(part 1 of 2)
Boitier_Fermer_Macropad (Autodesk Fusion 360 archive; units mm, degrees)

design "Coque/BoitierFermer v2" references "PCB5_Complex_Finale_Design"
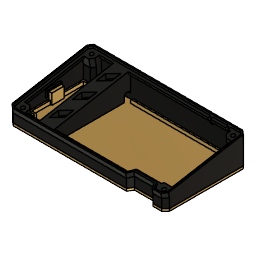
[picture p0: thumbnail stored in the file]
component_insert "Insertion d'un composant"
position "Position1"
sketch "Esquisse1" plane through (0, -7.3332, 41.5887) normal (0, 0.1736, -0.9848) x axis (-1, 0, 0)
  line L1 (-116.0418, -59.8204) -> (2.9981, -59.8204)
  line L2 (-118.0975, -61.9871) -> (-116.0418, -59.8204)
  line L3 (-118.0975, -121.6516) -> (-118.0975, -61.9871)
  line L4 (-115.692, -124.0571) -> (-118.0975, -121.6516)
  line L5 (-109.9203, -124.0571) -> (-115.692, -124.0571)
  line L6 (-107.7697, -120.1267) -> (-109.9203, -124.0571)
  line L7 (-89.721, -120.1201) -> (-107.7585, -120.1201)
  line L8 (-87.2075, -124.1841) -> (-89.7102, -120.1262)
  line L9 (3.0963, -124.1841) -> (-87.2075, -124.1841)
  line L10 (5.0673, -122.5451) -> (3.0963, -124.1841)
  line L11 (5.0673, -61.9929) -> (5.0673, -122.5451)
  line L12 (2.9981, -59.8204) -> (5.0673, -61.9929)
  line L13 (-2.3851, -76.6358) -> (-2.3851, -77.8358)
  line L14 (-0.3851, -77.8358) -> (-0.3851, -76.6358)
  line L15 (-13.585, -76.6358) -> (-13.585, -77.8358)
  line L16 (-11.585, -77.8358) -> (-11.585, -76.6358)
  line L17 (-109.1497, -125.3571) -> (-116.2304, -125.3571)
  line L18 (-106.9955, -121.4201) -> (-109.1497, -125.3571)
  line L19 (-90.4395, -121.4201) -> (-106.9955, -121.4201)
  line L20 (-87.9332, -125.4841) -> (-90.4395, -121.4201)
  line L21 (3.5662, -125.4841) -> (-87.9332, -125.4841)
  line L22 (6.3673, -123.1548) -> (3.5662, -125.4841)
  line L23 (6.3673, -61.4728) -> (6.3673, -123.1548)
  line L24 (3.5552, -58.5204) -> (6.3673, -61.4728)
  line L25 (-116.6004, -58.5204) -> (3.5552, -58.5204)
  line L26 (-119.3975, -61.4686) -> (-116.6004, -58.5204)
  line L27 (-119.3975, -122.1901) -> (-119.3975, -61.4686)
  line L28 (-116.2304, -125.3571) -> (-119.3975, -122.1901)
  line L29 (-107.4241, -120.1201) -> (-109.7424, -124.3571)
  line L30 (-107.5882, -120.4201) -> (-109.7424, -124.3571)
  line L31 (-109.7424, -124.3571) -> (-115.8162, -124.3571)
  line L32 (-115.8162, -124.3571) -> (-118.3975, -121.7758)
  line L33 (-118.3975, -121.7758) -> (-118.3975, -61.8675)
  line L34 (-118.3975, -61.8675) -> (-116.1707, -59.5204)
  line L35 (-116.1707, -59.5204) -> (3.1266, -59.5204)
  line L36 (3.1266, -59.5204) -> (5.3673, -61.8729)
  line L37 (5.3673, -61.8729) -> (5.3673, -122.6858)
  line L38 (5.3673, -122.6858) -> (3.2047, -124.4841)
  line L39 (3.2047, -124.4841) -> (-87.375, -124.4841)
  line L40 (-87.375, -124.4841) -> (-89.8813, -120.4201)
  line L41 (-90.0663, -120.1201) -> (-87.375, -124.4841)
  line L42 (-107.4241, -120.1201) -> (-90.0663, -120.1201)
  arc A1 centre (-107.7585, -120.1328) radius 0.0127 clockwise from (-107.7697, -120.1267) to (-107.7585, -120.1201)
  arc A2 centre (-89.721, -120.1328) radius 0.0127 clockwise from (-89.721, -120.1201) to (-89.7102, -120.1262)
  circle C1 centre (0.5, -63.7757) radius 1
  circle C2 centre (0.5, -120.2758) radius 1
  circle C3 centre (-6.985, -107.3058) radius 8.05
  arc A3 centre (-1.3851, -76.6358) radius 1 clockwise from (-2.3851, -76.6358) to (-0.3851, -76.6358)
  arc A4 centre (-1.3851, -77.8358) radius 1 clockwise from (-0.3851, -77.8358) to (-2.3851, -77.8358)
  circle C4 centre (-4.4849, -70.2356) radius 0.5
  circle C5 centre (-4.485, -84.7356) radius 0.5
  circle C6 centre (-6.985, -84.7356) radius 0.5
  circle C7 centre (-9.4849, -70.2356) radius 0.5
  circle C8 centre (-9.485, -84.7356) radius 0.5
  arc A5 centre (-12.585, -76.6358) radius 1 clockwise from (-13.585, -76.6358) to (-11.585, -76.6358)
  arc A6 centre (-12.585, -77.8358) radius 1 clockwise from (-11.585, -77.8358) to (-13.585, -77.8358)
  circle C9 centre (-31.0949, -91.1329) radius 1
  circle C10 centre (-31.0949, -72.0827) radius 1
  circle C11 centre (-31.0949, -110.1829) radius 1
  circle C12 centre (-36.5947, -91.1329) radius 1.75
  circle C13 centre (-36.5947, -72.0827) radius 1.75
  circle C14 centre (-36.5947, -110.1829) radius 1.75
  circle C15 centre (-36.5947, -85.233) radius 0.65
  circle C16 centre (-36.5947, -66.1828) radius 0.65
  circle C17 centre (-36.5947, -104.283) radius 0.65
  circle C18 centre (-37.3381, -93.8438) radius 0.1525
  circle C19 centre (-38.1001, -94.6058) radius 0.1525
  circle C20 centre (-38.7351, -95.3678) radius 0.1525
  circle C21 centre (-41.0211, -82.2868) radius 0.1525
  circle C22 centre (-41.0211, -84.3188) radius 0.1525
  circle C23 centre (-41.5948, -87.3328) radius 0.65
  circle C24 centre (-41.5948, -68.2826) radius 0.65
  circle C25 centre (-41.5948, -106.3828) radius 0.65
  circle C26 centre (-42.0949, -91.1329) radius 1
  circle C27 centre (-42.0949, -72.0827) radius 1
  circle C28 centre (-42.0949, -110.1829) radius 1
  circle C29 centre (-41.5291, -103.3688) radius 0.1525
  circle C30 centre (-41.5291, -101.2816) radius 0.1525
  circle C31 centre (-50.1452, -91.1329) radius 1
  circle C32 centre (-50.1452, -72.0827) radius 1
  circle C33 centre (-50.1452, -110.1829) radius 1
  circle C34 centre (-55.6451, -91.1329) radius 1.75
  circle C35 centre (-55.6451, -72.0827) radius 1.75
  circle C36 centre (-55.6451, -110.1829) radius 1.75
  circle C37 centre (-55.645, -85.233) radius 0.65
  circle C38 centre (-55.645, -66.1828) radius 0.65
  circle C39 centre (-55.645, -104.283) radius 0.65
  circle C40 centre (-60.1023, -84.2876) radius 0.1525
  circle C41 centre (-60.1023, -82.2556) radius 0.1525
  circle C42 centre (-60.6452, -87.3328) radius 0.65
  circle C43 centre (-60.6452, -68.2826) radius 0.65
  circle C44 centre (-60.6452, -106.3828) radius 0.65
  circle C45 centre (-61.1452, -91.1329) radius 1
  circle C46 centre (-61.1452, -72.0827) radius 1
  circle C47 centre (-61.1452, -110.1829) radius 1
  circle C48 centre (-60.5791, -101.3092) radius 0.1525
  circle C49 centre (-60.5791, -103.3964) radius 0.1525
  circle C50 centre (-69.1953, -91.1329) radius 1
  circle C51 centre (-69.1953, -72.0827) radius 1
  circle C52 centre (-69.1953, -110.1829) radius 1
  circle C53 centre (-74.6952, -91.1329) radius 1.75
  circle C54 centre (-74.6952, -72.0827) radius 1.75
  circle C55 centre (-74.6952, -110.1829) radius 1.75
  circle C56 centre (-74.6951, -85.233) radius 0.65
  circle C57 centre (-74.6951, -66.1828) radius 0.65
  circle C58 centre (-74.6951, -104.283) radius 0.65
  circle C59 centre (-78.7402, -95.3678) radius 0.1525
  circle C60 centre (-79.0883, -84.3357) radius 0.1525
  circle C61 centre (-79.1049, -82.2399) radius 0.1525
  circle C62 centre (-79.6953, -87.3328) radius 0.65
  circle C63 centre (-79.6953, -68.2826) radius 0.65
  circle C64 centre (-79.6953, -106.3828) radius 0.65
  circle C65 centre (-80.1953, -91.1329) radius 1
  circle C66 centre (-80.1953, -72.0827) radius 1
  circle C67 centre (-80.1953, -110.1829) radius 1
  circle C68 centre (-79.5022, -94.6058) radius 0.1525
  circle C69 centre (-79.6292, -101.1822) radius 0.1525
  circle C70 centre (-79.6292, -103.2694) radius 0.1525
  circle C71 centre (-80.2642, -93.8438) radius 0.1525
  circle C72 centre (-86.1062, -92.9548) radius 0.1525
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  point P156 (-107.4241, -120.1201)
  point P169 (-90.0663, -120.1201)
  coincident L7 P156
  coincident L7 P169
  parallel L40 L41
  dimension "d1" = 0.3
  dimension "d2" = 1.3 (= "1.00 mm + 0.3 mm")
  dimension "d3" = 0.3
extrude "Extrusion1" new body sketch "Esquisse1" profile of L7 L28 L25 L18 L23 L20 L22 L26 L21 L19 L27 L24 L17 L29 L32 L30 L33 L31 L34 L37 L40 L39 L38 L36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 against normal blind 1.7
sketch "Esquisse2" plane through (0, -7.3332, 41.5887) normal (0, 0.1736, -0.9848) x axis (-1, 0, 0)
  line L1 (-87.375, -124.4841) -> (3.2047, -124.4841)
  line L2 (-90.0663, -120.1201) -> (-87.375, -124.4841)
  line L3 (-107.4241, -120.1201) -> (-90.0663, -120.1201)
  line L4 (-109.7424, -124.3571) -> (-107.4241, -120.1201)
  line L5 (-115.8162, -124.3571) -> (-109.7424, -124.3571)
  line L6 (-118.3975, -121.7758) -> (-115.8162, -124.3571)
  line L7 (-118.3975, -61.8675) -> (-118.3975, -121.7758)
  line L8 (-116.1707, -59.5204) -> (-118.3975, -61.8675)
  line L9 (3.1266, -59.5204) -> (-116.1707, -59.5204)
  line L10 (5.3673, -61.8729) -> (3.1266, -59.5204)
  line L11 (5.3673, -122.6858) -> (5.3673, -61.8729)
  line L12 (3.2047, -124.4841) -> (5.3673, -122.6858)
  line L13 (-116.2304, -125.3571) -> (-119.3975, -122.1901)
  line L14 (-109.1497, -125.3571) -> (-116.2304, -125.3571)
  line L15 (-106.9955, -121.4201) -> (-109.1497, -125.3571)
  line L16 (-90.4395, -121.4201) -> (-106.9955, -121.4201)
  line L17 (-87.9332, -125.4841) -> (-90.4395, -121.4201)
  line L18 (3.5662, -125.4841) -> (-87.9332, -125.4841)
  line L19 (6.3673, -123.1548) -> (3.5662, -125.4841)
  line L20 (6.3673, -61.4728) -> (6.3673, -123.1548)
  line L21 (3.5552, -58.5204) -> (6.3673, -61.4728)
  line L22 (-116.6004, -58.5204) -> (3.5552, -58.5204)
  line L23 (-119.3975, -61.4686) -> (-116.6004, -58.5204)
  line L24 (-119.3975, -122.1901) -> (-119.3975, -61.4686)
  line L25 (-86.0912, -122.1841) -> (2.3734, -122.1841)
  line L26 (-88.7826, -117.8201) -> (-86.0912, -122.1841)
  line L27 (-108.7874, -117.8201) -> (-88.7826, -117.8201)
  line L28 (-111.1057, -122.0571) -> (-108.7874, -117.8201)
  line L29 (-114.8635, -122.0571) -> (-111.1057, -122.0571)
  line L30 (-116.0975, -120.8232) -> (-114.8635, -122.0571)
  line L31 (-116.0975, -62.7849) -> (-116.0975, -120.8232)
  line L32 (-115.1824, -61.8204) -> (-116.0975, -62.7849)
  line L33 (2.141, -61.8204) -> (-115.1824, -61.8204)
  line L34 (3.0673, -62.7929) -> (2.141, -61.8204)
  line L35 (3.0673, -121.6071) -> (3.0673, -62.7929)
  line L36 (2.3734, -122.1841) -> (3.0673, -121.6071)
  dimension "d6" = 2.3 (= "2.00 mm + 0.3 mm")
extrude "Extrusion2" add sketch "Esquisse2" along normal blind 2
position "Position2"
work_plane "Plan de construction1" RotateAngle 0
sketch "Esquisse3" plane through (0, 0, 17.829) normal (0, 0, 1) x axis (1, 0, 0)
  line L1 (-3.0673, -126.7455) -> (-3.0673, -68.8249)
  line L2 (-2.3734, -127.3138) -> (-3.0673, -126.7455)
  line L3 (86.0912, -127.3138) -> (-2.3734, -127.3138)
  line L4 (88.7826, -123.0161) -> (86.0912, -127.3138)
  line L5 (108.7874, -123.0161) -> (88.7826, -123.0161)
  line L6 (111.1057, -127.1887) -> (108.7874, -123.0161)
  line L7 (114.8635, -127.1887) -> (111.1057, -127.1887)
  line L8 (116.0975, -125.9735) -> (114.8635, -127.1887)
  line L9 (116.0975, -68.817) -> (116.0975, -125.9735)
  line L10 (115.1824, -67.8671) -> (116.0975, -68.817)
  line L11 (-2.141, -67.8671) -> (115.1824, -67.8671)
  line L12 (-3.0673, -68.8249) -> (-2.141, -67.8671)
  line L13 (119.3975, -127.3196) -> (119.3975, -67.5206)
  line L14 (116.2304, -130.4386) -> (119.3975, -127.3196)
  line L15 (109.1497, -130.4386) -> (116.2304, -130.4386)
  line L16 (106.9955, -126.5614) -> (109.1497, -130.4386)
  line L17 (90.4395, -126.5614) -> (106.9955, -126.5614)
  line L18 (87.9332, -130.5637) -> (90.4395, -126.5614)
  line L19 (-3.5662, -130.5637) -> (87.9332, -130.5637)
  line L20 (-6.3673, -128.2697) -> (-3.5662, -130.5637)
  line L21 (-6.3673, -67.5248) -> (-6.3673, -128.2697)
  line L22 (-3.5552, -64.6173) -> (-6.3673, -67.5248)
  line L23 (116.6004, -64.6173) -> (-3.5552, -64.6173)
  line L24 (119.3975, -67.5206) -> (116.6004, -64.6173)
extrude "Extrusion3" new body sketch "Esquisse3" against normal blind 1
sketch "Esquisse4" plane through (0, 0, 17.829) normal (0, 0, 1) x axis (-1, 0, 0)
  line L1 (2.141, 67.8671) -> (3.0673, 68.8249)
  line L2 (-115.1824, 67.8671) -> (2.141, 67.8671)
  line L3 (-116.0975, 68.817) -> (-115.1824, 67.8671)
  line L4 (-116.0975, 125.9735) -> (-116.0975, 68.817)
  line L5 (-114.8635, 127.1887) -> (-116.0975, 125.9735)
  line L6 (-111.1057, 127.1887) -> (-114.8635, 127.1887)
  line L7 (-108.7874, 123.0161) -> (-111.1057, 127.1887)
  line L8 (-88.7826, 123.0161) -> (-108.7874, 123.0161)
  line L9 (-86.0912, 127.3138) -> (-88.7826, 123.0161)
  line L10 (2.3734, 127.3138) -> (-86.0912, 127.3138)
  line L11 (3.0673, 126.7455) -> (2.3734, 127.3138)
  line L12 (3.0673, 68.8249) -> (3.0673, 126.7455)
  line L13 (3.5552, 64.6173) -> (-116.6004, 64.6173)
  line L14 (6.3673, 67.5248) -> (3.5552, 64.6173)
  line L15 (6.3673, 128.2697) -> (6.3673, 67.5248)
  line L16 (3.5662, 130.5637) -> (6.3673, 128.2697)
  line L17 (-87.9332, 130.5637) -> (3.5662, 130.5637)
  line L18 (-90.4395, 126.5614) -> (-87.9332, 130.5637)
  line L19 (-106.9955, 126.5614) -> (-90.4395, 126.5614)
  line L20 (-109.1497, 130.4386) -> (-106.9955, 126.5614)
  line L21 (-116.2304, 130.4386) -> (-109.1497, 130.4386)
  line L22 (-119.3975, 127.3196) -> (-116.2304, 130.4386)
  line L23 (-119.3975, 67.5206) -> (-119.3975, 127.3196)
  line L24 (-116.6004, 64.6173) -> (-119.3975, 67.5206)
  line L25 (2.141, 67.8671) -> (3.5552, 64.6173)
  line L26 (6.3673, 67.5248) -> (3.0673, 68.8249)
  line L27 (-115.1824, 67.8671) -> (-116.6004, 64.6173)
  line L28 (-119.3975, 67.5206) -> (-116.0975, 68.817)
  line L29 (-116.0975, 125.9735) -> (-119.3975, 127.3196)
  line L30 (-114.8635, 127.1887) -> (-116.2304, 130.4386)
  line L31 (-111.1057, 127.1887) -> (-109.1497, 130.4386)
  line L32 (-108.7874, 123.0161) -> (-106.9955, 126.5614)
  line L33 (-88.7826, 123.0161) -> (-90.4395, 126.5614)
  line L34 (-86.0912, 127.3138) -> (-87.9332, 130.5637)
  line L35 (2.3734, 127.3138) -> (3.5662, 130.5637)
  line L36 (6.3673, 128.2697) -> (3.0673, 126.7455)
  point P15 (3.5552, 64.6173)
  point P26 (3.5552, 64.6173)
  point P3 (2.141, 67.8671)
  point P27 (2.141, 67.8671)
  point P2 (3.0673, 68.8249)
  point P28 (3.0673, 68.8249)
  point P16 (6.3673, 67.5248)
  point P29 (6.3673, 67.5248)
  point P14 (-116.6004, 64.6173)
  point P30 (-116.6004, 64.6173)
  point P4 (-115.1824, 67.8671)
  point P31 (-115.1824, 67.8671)
  point P5 (-116.0975, 68.817)
  point P32 (-116.0975, 68.817)
  point P25 (-119.3975, 67.5206)
  point P33 (-119.3975, 67.5206)
  point P24 (-119.3975, 127.3196)
  point P34 (-119.3975, 127.3196)
  point P6 (-116.0975, 125.9735)
  point P35 (-116.0975, 125.9735)
  point P23 (-116.2304, 130.4386)
  point P36 (-116.2304, 130.4386)
  point P7 (-114.8635, 127.1887)
  point P37 (-114.8635, 127.1887)
  point P22 (-109.1497, 130.4386)
  point P38 (-109.1497, 130.4386)
  point P8 (-111.1057, 127.1887)
  point P39 (-111.1057, 127.1887)
  point P21 (-106.9955, 126.5614)
  point P40 (-106.9955, 126.5614)
  point P9 (-108.7874, 123.0161)
  point P41 (-108.7874, 123.0161)
  point P20 (-90.4395, 126.5614)
  point P42 (-90.4395, 126.5614)
  point P10 (-88.7826, 123.0161)
  point P43 (-88.7826, 123.0161)
  point P19 (-87.9332, 130.5637)
  point P44 (-87.9332, 130.5637)
  point P11 (-86.0912, 127.3138)
  point P45 (-86.0912, 127.3138)
  point P18 (3.5662, 130.5637)
  point P46 (3.5662, 130.5637)
  point P12 (2.3734, 127.3138)
  point P47 (2.3734, 127.3138)
  point P13 (3.0673, 126.7455)
  point P48 (3.0673, 126.7455)
  point P17 (6.3673, 128.2697)
  point P49 (6.3673, 128.2697)
  coincident P15 P26
  coincident P3 P27
  coincident P2 P28
  coincident P16 P29
  coincident P14 P30
  coincident P4 P31
  coincident P5 P32
  coincident P25 P33
  coincident P24 P34
  coincident P6 P35
  coincident P23 P36
  coincident P7 P37
  coincident P22 P38
  coincident P8 P39
  coincident P21 P40
  coincident P9 P41
  coincident P20 P42
  coincident P10 P43
  coincident P19 P44
  coincident P11 P45
  coincident P18 P46
  coincident P12 P47
  coincident P13 P48
  coincident P17 P49
sketch "Esquisse5" plane through (0, -6.9859, 39.619) normal (0, 0.1736, -0.9848) x axis (-1, 0, 0)
  line L1 (3.0673, -121.6071) -> (3.0673, -62.7929)
  line L2 (2.3734, -122.1841) -> (3.0673, -121.6071)
  line L3 (-86.0912, -122.1841) -> (2.3734, -122.1841)
  line L4 (-88.7826, -117.8201) -> (-86.0912, -122.1841)
  line L5 (-108.7874, -117.8201) -> (-88.7826, -117.8201)
  line L6 (-111.1057, -122.0571) -> (-108.7874, -117.8201)
  line L7 (-114.8635, -122.0571) -> (-111.1057, -122.0571)
  line L8 (-116.0975, -120.8232) -> (-114.8635, -122.0571)
  line L9 (-116.0975, -62.7849) -> (-116.0975, -120.8232)
  line L10 (-115.1824, -61.8204) -> (-116.0975, -62.7849)
  line L11 (2.141, -61.8204) -> (-115.1824, -61.8204)
  line L12 (3.0673, -62.7929) -> (2.141, -61.8204)
  line L13 (-119.3975, -122.1901) -> (-119.3975, -61.4686)
  line L14 (-116.2304, -125.3571) -> (-119.3975, -122.1901)
  line L15 (-109.1497, -125.3571) -> (-116.2304, -125.3571)
  line L16 (-106.9955, -121.4201) -> (-109.1497, -125.3571)
  line L17 (-90.4395, -121.4201) -> (-106.9955, -121.4201)
  line L18 (-87.9332, -125.4841) -> (-90.4395, -121.4201)
  line L19 (3.5662, -125.4841) -> (-87.9332, -125.4841)
  line L20 (6.3673, -123.1548) -> (3.5662, -125.4841)
  line L21 (6.3673, -61.4728) -> (6.3673, -123.1548)
  line L22 (3.5552, -58.5204) -> (6.3673, -61.4728)
  line L23 (-116.6004, -58.5204) -> (3.5552, -58.5204)
  line L24 (-119.3975, -61.4686) -> (-116.6004, -58.5204)
  line L25 (3.5552, -58.5204) -> (2.141, -61.8204)
  line L26 (6.3673, -61.4728) -> (3.0673, -62.7929)
  line L27 (-119.3975, -61.4686) -> (-116.0975, -62.7849)
  line L28 (-116.6004, -58.5204) -> (-115.1824, -61.8204)
  line L29 (6.3673, -123.1548) -> (3.0673, -121.6071)
  line L30 (2.3734, -122.1841) -> (3.5662, -125.4841)
  line L31 (-86.0912, -122.1841) -> (-87.9332, -125.4841)
  line L32 (-88.7826, -117.8201) -> (-90.4395, -121.4201)
  line L33 (-108.7874, -117.8201) -> (-106.9955, -121.4201)
  line L34 (-111.1057, -122.0571) -> (-109.1497, -125.3571)
  line L35 (-114.8635, -122.0571) -> (-116.2304, -125.3571)
  line L36 (-119.3975, -122.1901) -> (-116.0975, -120.8232)
  point P13 (2.141, -61.8204)
  point P26 (2.141, -61.8204)
  point P24 (3.5552, -58.5204)
  point P27 (3.5552, -58.5204)
  point P2 (3.0673, -62.7929)
  point P28 (3.0673, -62.7929)
  point P23 (6.3673, -61.4728)
  point P29 (6.3673, -61.4728)
  point P11 (-116.0975, -62.7849)
  point P30 (-116.0975, -62.7849)
  point P14 (-119.3975, -61.4686)
  point P31 (-119.3975, -61.4686)
  point P12 (-115.1824, -61.8204)
  point P32 (-115.1824, -61.8204)
  point P25 (-116.6004, -58.5204)
  point P33 (-116.6004, -58.5204)
  point P3 (3.0673, -121.6071)
  point P34 (3.0673, -121.6071)
  point P22 (6.3673, -123.1548)
  point P35 (6.3673, -123.1548)
  point P21 (3.5662, -125.4841)
  point P36 (3.5662, -125.4841)
  point P4 (2.3734, -122.1841)
  point P37 (2.3734, -122.1841)
  point P20 (-87.9332, -125.4841)
  point P38 (-87.9332, -125.4841)
  point P5 (-86.0912, -122.1841)
  point P39 (-86.0912, -122.1841)
  point P19 (-90.4395, -121.4201)
  point P40 (-90.4395, -121.4201)
  point P6 (-88.7826, -117.8201)
  point P41 (-88.7826, -117.8201)
  point P18 (-106.9955, -121.4201)
  point P42 (-106.9955, -121.4201)
  point P7 (-108.7874, -117.8201)
  point P43 (-108.7874, -117.8201)
  point P17 (-109.1497, -125.3571)
  point P44 (-109.1497, -125.3571)
  point P8 (-111.1057, -122.0571)
  point P45 (-111.1057, -122.0571)
  point P16 (-116.2304, -125.3571)
  point P46 (-116.2304, -125.3571)
  point P9 (-114.8635, -122.0571)
  point P47 (-114.8635, -122.0571)
  point P10 (-116.0975, -120.8232)
  point P48 (-116.0975, -120.8232)
  point P15 (-119.3975, -122.1901)
  point P49 (-119.3975, -122.1901)
  coincident P13 P26
  coincident P24 P27
  coincident P2 P28
  coincident P23 P29
  coincident P11 P30
  coincident P14 P31
  coincident P12 P32
  coincident P25 P33
  coincident P3 P34
  coincident P22 P35
  coincident P21 P36
  coincident P4 P37
  coincident P20 P38
  coincident P5 P39
  coincident P19 P40
  coincident P6 P41
  coincident P18 P42
  coincident P7 P43
  coincident P17 P44
  coincident P8 P45
  coincident P16 P46
  coincident P9 P47
  coincident P10 P48
  coincident P15 P49
loft "Lissage1" sketch "Esquisse4" + "Esquisse5"
loft "Lissage2" sketch "Esquisse4" + "Esquisse5"
loft "Lissage3" sketch "Esquisse5" + "Esquisse4"
loft "Lissage4" sketch "Esquisse4" + "Esquisse5"
loft "Lissage7" sketch "Esquisse4" + "Esquisse5"
loft "Lissage8" sketch "Esquisse4" + "Esquisse5"
loft "Lissage9" sketch "Esquisse4" + "Esquisse5"
loft "Lissage10" sketch "Esquisse4" + "Esquisse5"
loft "Lissage11" sketch "Esquisse4" + "Esquisse5"
loft "Lissage12" sketch "Esquisse4" + "Esquisse5"
loft "Lissage13" sketch "Esquisse5" + "Esquisse4"
loft "Lissage14" sketch "Esquisse4" + "Esquisse5"
combine "Combiner"
sketch "Esquisse6" plane through (0, -7.6284, 43.2628) normal (0, -0.1736, 0.9848) x axis (1, 0, 0)
  line L1 (-3.2047, -124.4841) -> (87.375, -124.4841)
  line L2 (-5.3673, -122.6858) -> (-3.2047, -124.4841)
  line L3 (-5.3673, -61.8729) -> (-5.3673, -122.6858)
  line L4 (-3.1266, -59.5204) -> (-5.3673, -61.8729)
  line L5 (116.1707, -59.5204) -> (-3.1266, -59.5204)
  line L6 (118.3975, -61.8675) -> (116.1707, -59.5204)
  line L7 (118.3975, -121.7758) -> (118.3975, -61.8675)
  line L8 (115.8162, -124.3571) -> (118.3975, -121.7758)
  line L9 (109.7424, -124.3571) -> (115.8162, -124.3571)
  line L10 (107.4241, -120.1201) -> (109.7424, -124.3571)
  line L11 (90.0663, -120.1201) -> (107.4241, -120.1201)
  line L12 (87.375, -124.4841) -> (90.0663, -120.1201)
  line L13 (119.3975, -122.1901) -> (116.2304, -125.3571)
  line L14 (119.3975, -61.4686) -> (119.3975, -122.1901)
  line L15 (116.6004, -58.5204) -> (119.3975, -61.4686)
  line L16 (-3.5552, -58.5204) -> (116.6004, -58.5204)
  line L17 (-6.3673, -61.4728) -> (-3.5552, -58.5204)
  line L18 (-6.3673, -123.1548) -> (-6.3673, -61.4728)
  line L19 (-3.5662, -125.4841) -> (-6.3673, -123.1548)
  line L20 (87.9332, -125.4841) -> (-3.5662, -125.4841)
  line L21 (90.4395, -121.4201) -> (87.9332, -125.4841)
  line L22 (106.9955, -121.4201) -> (90.4395, -121.4201)
  line L23 (109.1497, -125.3571) -> (106.9955, -121.4201)
  line L24 (116.2304, -125.3571) -> (109.1497, -125.3571)
  line L25 (108.1, -120.1201) -> (106.5802, -120.1201)
  line L26 (107.7241, -120.1201) -> (109.7424, -124.3571)
  line L27 (107.4241, -120.1201) -> (107.7241, -120.1201)
  line L28 (109.7424, -124.3571) -> (107.4241, -120.1201)
  point P26 (106.5802, -120.1201)
  point P11 (109.7424, -124.3571)
  point P28 (109.7424, -124.3571)
  point P29 (107.7241, -120.1201)
  point P12 (107.4241, -120.1201)
  point P30 (107.4241, -120.1201)
  coincident L11 P26
  coincident P11 P28
  coincident L25 P29
  coincident P12 P30
  parallel L11 L27
  dimension "d12" distance P12 P29 = 0.3
extrude "Extrusion4" add sketch "Esquisse6" profile of L10 L26 L27 L28 against normal blind 1.7
extrude "Extrusion5" add of existing geometry blind 0.3
extrude "Extrusion6" add of existing geometry blind 5
extrude "Extrusion7" cut of existing geometry blind -1.5
sketch "Esquisse7" plane through (-3.0673, 0, 0) normal (1, 0, 0) x axis (0, 1, 0)
  line L1 (-127.0928, 20.4718) -> (-69.1722, 30.6848)
  line L2 (-126.7455, 18.5022) -> (-127.0928, 20.4718)
  line L3 (-126.7455, 11.829) -> (-126.7455, 18.5022)
  line L4 (-68.8249, 11.829) -> (-126.7455, 11.829)
  line L5 (-68.8249, 28.7152) -> (-68.8249, 11.829)
  line L6 (-69.1722, 30.6848) -> (-68.8249, 28.7152)
  line L7 (-68.8249, 28.7152) -> (-126.7455, 18.5022)
  point P4 (-126.7455, 18.5022)
  point P8 (-126.7455, 18.5022)
  point P7 (-68.8249, 28.7152)
  point P9 (-68.8249, 28.7152)
  coincident P4 P8
  coincident P7 P9
extrude "Extrusion8" cut sketch "Esquisse7" profile of L3 L4 L5 L7 against normal blind 1.5
sketch "Esquisse8" plane through (116.0975, 0, 0) normal (-1, 0, 0) x axis (0, -1, 0)
  line L1 (69.1643, 30.6862) -> (126.3208, 20.6079)
  line L2 (68.817, 28.7166) -> (69.1643, 30.6862)
  line L3 (68.817, 11.829) -> (68.817, 28.7166)
  line L4 (125.9735, 11.829) -> (68.817, 11.829)
  line L5 (125.9735, 18.6383) -> (125.9735, 11.829)
  line L6 (126.3208, 20.6079) -> (125.9735, 18.6383)
  line L7 (68.817, 28.7166) -> (125.9735, 18.6383)
  point P7 (125.9735, 18.6383)
  point P8 (125.9735, 18.6383)
  point P4 (68.817, 28.7166)
  point P9 (68.817, 28.7166)
  coincident P7 P8
  coincident P4 P9
extrude "Extrusion9" cut sketch "Esquisse8" profile of L3 L4 L5 L7 against normal blind 1.5
sketch "Esquisse9" plane through (0, 0, 11.829) normal (0, 0, -1) x axis (1, 0, 0)
  line L1 (117.5975, 125.9735) -> (116.0975, 125.9735)
  line L2 (117.5975, 68.817) -> (117.5975, 125.9735)
  line L3 (116.0975, 68.817) -> (117.5975, 68.817)
  line L4 (115.1824, 67.8671) -> (116.0975, 68.817)
  line L5 (115.1824, 66.3671) -> (115.1824, 67.8671)
  line L6 (-2.141, 66.3671) -> (115.1824, 66.3671)
  line L7 (-2.141, 67.8671) -> (-2.141, 66.3671)
  line L8 (-3.0673, 68.8249) -> (-2.141, 67.8671)
  line L9 (-4.5673, 68.8249) -> (-3.0673, 68.8249)
  line L10 (-4.5673, 126.7455) -> (-4.5673, 68.8249)
  line L11 (-3.0673, 126.7455) -> (-4.5673, 126.7455)
  line L12 (-2.3734, 127.3138) -> (-3.0673, 126.7455)
  line L13 (86.0912, 127.3138) -> (-2.3734, 127.3138)
  line L14 (88.7826, 123.0161) -> (86.0912, 127.3138)
  line L15 (108.7874, 123.0161) -> (88.7826, 123.0161)
  line L16 (111.1057, 127.1887) -> (108.7874, 123.0161)
  line L17 (114.8635, 127.1887) -> (111.1057, 127.1887)
  line L18 (116.0975, 125.9735) -> (114.8635, 127.1887)
  line L19 (116.6004, 64.6173) -> (-3.5552, 64.6173)
  line L20 (119.3975, 67.5206) -> (116.6004, 64.6173)
  line L21 (119.3975, 127.3196) -> (119.3975, 67.5206)
  line L22 (116.2304, 130.4386) -> (119.3975, 127.3196)
  line L23 (109.1497, 130.4386) -> (116.2304, 130.4386)
  line L24 (106.9955, 126.5614) -> (109.1497, 130.4386)
  line L25 (90.4395, 126.5614) -> (106.9955, 126.5614)
  line L26 (87.9332, 130.5637) -> (90.4395, 126.5614)
  line L27 (-3.5662, 130.5637) -> (87.9332, 130.5637)
  line L28 (-6.3673, 128.2697) -> (-3.5662, 130.5637)
  line L29 (-6.3673, 67.5248) -> (-6.3673, 128.2697)
  line L30 (-3.5552, 64.6173) -> (-6.3673, 67.5248)
  line L31 (114.8635, 130.4386) -> (114.8635, 127.1887)
  line L32 (-2.3734, 130.5637) -> (-2.3734, 127.3138)
  line L33 (115.4781, 128.6887) -> (110.2232, 128.6887)
  line L34 (116.7121, 127.4735) -> (115.4781, 128.6887)
  line L35 (119.0975, 127.4735) -> (116.7121, 127.4735)
  line L36 (119.0975, 67.317) -> (119.0975, 127.4735)
  line L37 (116.7353, 67.317) -> (119.0975, 67.317)
  line L38 (116.6824, 67.2621) -> (116.7353, 67.317)
  line L39 (116.6824, 64.8671) -> (116.6824, 67.2621)
  line L40 (-3.641, 64.8671) -> (116.6824, 64.8671)
  line L41 (-3.641, 67.2604) -> (-3.641, 64.8671)
  line L42 (-3.7033, 67.3249) -> (-3.641, 67.2604)
  line L43 (-6.0673, 67.3249) -> (-3.7033, 67.3249)
  line L44 (-6.0673, 128.2455) -> (-6.0673, 67.3249)
  line L45 (-3.6031, 128.2455) -> (-6.0673, 128.2455)
  line L46 (-2.9092, 128.8138) -> (-3.6031, 128.2455)
  line L47 (86.9217, 128.8138) -> (-2.9092, 128.8138)
  line L48 (89.6131, 124.5161) -> (86.9217, 128.8138)
  line L49 (107.9048, 124.5161) -> (89.6131, 124.5161)
  line L50 (110.2232, 128.6887) -> (107.9048, 124.5161)
  point P19 (114.8635, 127.1887)
  point P32 (114.8635, 127.1887)
  point P33 (114.8635, 130.4386)
  point P14 (-2.3734, 127.3138)
  point P34 (-2.3734, 127.3138)
  point P35 (-2.3734, 130.5637)
  coincident P19 P32
  coincident L23 P33
  perpendicular L23 L31
  coincident P14 P34
  coincident L27 P35
  perpendicular L27 L32
  dimension "d25" = -1.5
extrude "Extrusion10" cut sketch "Esquisse9" profile of L13 L14 L15 L16 L17 L31 L32 L48 L49 L33 L50 L47 against normal blind 7
sketch "Esquisse10" plane through (117.5975, 0, 0) normal (-1, 0, 0) x axis (0, -1, 0)
  line L1 (68.817, 28.7166) -> (125.9735, 18.6383)
  line L2 (68.817, 11.829) -> (68.817, 28.7166)
  line L3 (125.9735, 11.829) -> (68.817, 11.829)
  line L4 (125.9735, 18.6383) -> (125.9735, 11.829)
  line L5 (124.8924, 18.829) -> (123.0161, 18.829)
  line L6 (123.0161, 19.1598) -> (124.8924, 18.829)
  line L7 (123.0161, 18.829) -> (123.0161, 19.1598)
extrude "Extrusion11" cut sketch "Esquisse10" profile of L1 L5 L6 L7 along normal blind 31.5
sketch "Esquisse11" plane through (0, -7.3332, 41.5887) normal (0, -0.1736, 0.9848) x axis (1, 0, 0)
  line L1 (107.7241, -120.1201) -> (90.0663, -120.1201)
  line L2 (109.7424, -124.3571) -> (107.7241, -120.1201)
  line L3 (115.8162, -124.3571) -> (109.7424, -124.3571)
  line L4 (118.3975, -121.7758) -> (115.8162, -124.3571)
  line L5 (118.3975, -61.8675) -> (118.3975, -121.7758)
  line L6 (116.1707, -59.5204) -> (118.3975, -61.8675)
  line L7 (-3.1266, -59.5204) -> (116.1707, -59.5204)
  line L8 (-5.3673, -61.8729) -> (-3.1266, -59.5204)
  line L9 (-5.3673, -122.6858) -> (-5.3673, -61.8729)
  line L10 (-3.2047, -124.4841) -> (-5.3673, -122.6858)
  line L11 (87.375, -124.4841) -> (-3.2047, -124.4841)
  line L12 (90.0663, -120.1201) -> (87.375, -124.4841)
  line L13 (-3.0673, -62.7929) -> (-3.0673, -121.6071)
  line L14 (-2.141, -61.8204) -> (-3.0673, -62.7929)
  line L15 (115.1824, -61.8204) -> (-2.141, -61.8204)
  line L16 (116.0975, -62.7849) -> (115.1824, -61.8204)
  line L17 (116.0975, -120.8232) -> (116.0975, -62.7849)
  line L18 (114.8635, -122.0571) -> (116.0975, -120.8232)
  line L19 (111.1057, -122.0571) -> (114.8635, -122.0571)
  line L20 (108.7874, -117.8201) -> (111.1057, -122.0571)
  line L21 (88.7826, -117.8201) -> (108.7874, -117.8201)
  line L22 (86.0912, -122.1841) -> (88.7826, -117.8201)
  line L23 (-2.3734, -122.1841) -> (86.0912, -122.1841)
  line L24 (-3.0673, -121.6071) -> (-2.3734, -122.1841)
  line L25 (-2.9981, -59.8204) -> (116.0418, -59.8204)
  line L26 (-5.0673, -61.9929) -> (-2.9981, -59.8204)
  line L27 (-5.0673, -122.5451) -> (-5.0673, -61.9929)
  line L28 (-3.0963, -124.1841) -> (-5.0673, -122.5451)
  line L29 (87.2075, -124.1841) -> (-3.0963, -124.1841)
  line L30 (89.7102, -120.1262) -> (87.2075, -124.1841)
  line L31 (107.7585, -120.1201) -> (89.721, -120.1201)
  line L32 (109.9203, -124.0571) -> (107.7697, -120.1267)
  line L33 (115.692, -124.0571) -> (109.9203, -124.0571)
  line L34 (118.0975, -121.6516) -> (115.692, -124.0571)
  line L35 (118.0975, -61.9871) -> (118.0975, -121.6516)
  line L36 (116.0418, -59.8204) -> (118.0975, -61.9871)
  line L37 (2.3851, -77.8358) -> (2.3851, -76.6358)
  line L38 (0.3851, -76.6358) -> (0.3851, -77.8358)
  line L39 (13.585, -77.8358) -> (13.585, -76.6358)
  line L40 (11.585, -76.6358) -> (11.585, -77.8358)
  line L41 (-0.5, -63.7757) -> (113.6352, -63.7757)
  line L42 (56.5676, -132) -> (56.5676, -63.7757)
  line L43 (3.5, -63.7757) -> (-0.5, -63.7757)
  line L44 (2.5, -120.2758) -> (-0.5, -120.2758)
  line L45 (-0.5, -116.2758) -> (-0.5, -120.2758)
  line L46 (-0.5, -67.7757) -> (-0.5, -63.7757)
  line L47 (3.5, -67.7757) -> (-5.3673, -67.7757)
  line L48 (3.5, -59.5204) -> (3.5, -67.7757)
  line L49 (3.5, -116.2758) -> (3.5, -124.4841)
  line L50 (-5.3673, -116.2758) -> (3.5, -116.2758)
  line L51 (109.6352, -59.5204) -> (109.6352, -67.7757)
  line L52 (109.6352, -67.7757) -> (118.5025, -67.7757)
  line L53 (113.6352, -116.2758) -> (113.6352, -120.2758)
  line L54 (109.6352, -116.2758) -> (113.6352, -116.2758)
  line L55 (109.6352, -116.2758) -> (118.3975, -116.2758)
  line L56 (109.6352, -124.3571) -> (109.6352, -116.2758)
  line L57 (108.7874, -117.8201) -> (109.6352, -116.2758)
  arc A1 centre (89.721, -120.1328) radius 0.0127 clockwise from (89.7102, -120.1262) to (89.721, -120.1201)
  arc A2 centre (107.7585, -120.1328) radius 0.0127 clockwise from (107.7585, -120.1201) to (107.7697, -120.1267)
  circle C1 centre (-0.5, -63.7757) radius 1
  circle C2 centre (-0.5, -120.2758) radius 1
  circle C3 centre (6.985, -107.3058) radius 8.05
  arc A3 centre (1.3851, -77.8358) radius 1 clockwise from (2.3851, -77.8358) to (0.3851, -77.8358)
  arc A4 centre (1.3851, -76.6358) radius 1 clockwise from (0.3851, -76.6358) to (2.3851, -76.6358)
  circle C4 centre (4.4849, -70.2356) radius 0.5
  circle C5 centre (4.485, -84.7356) radius 0.5
  circle C6 centre (6.985, -84.7356) radius 0.5
  circle C7 centre (9.4849, -70.2356) radius 0.5
  circle C8 centre (9.485, -84.7356) radius 0.5
  arc A5 centre (12.585, -77.8358) radius 1 clockwise from (13.585, -77.8358) to (11.585, -77.8358)
  arc A6 centre (12.585, -76.6358) radius 1 clockwise from (11.585, -76.6358) to (13.585, -76.6358)
  circle C9 centre (31.0949, -91.1329) radius 1
  circle C10 centre (31.0949, -72.0827) radius 1
  circle C11 centre (31.0949, -110.1829) radius 1
  circle C12 centre (36.5947, -91.1329) radius 1.75
  circle C13 centre (36.5947, -72.0827) radius 1.75
  circle C14 centre (36.5947, -110.1829) radius 1.75
  circle C15 centre (36.5947, -85.233) radius 0.65
  circle C16 centre (36.5947, -66.1828) radius 0.65
  circle C17 centre (36.5947, -104.283) radius 0.65
  circle C18 centre (37.3381, -93.8438) radius 0.1525
  circle C19 centre (38.1001, -94.6058) radius 0.1525
  circle C20 centre (38.7351, -95.3678) radius 0.1525
  circle C21 centre (41.0211, -82.2868) radius 0.1525
  circle C22 centre (41.0211, -84.3188) radius 0.1525
  circle C23 centre (41.5948, -87.3328) radius 0.65
  circle C24 centre (41.5948, -68.2826) radius 0.65
  circle C25 centre (41.5948, -106.3828) radius 0.65
  circle C26 centre (42.0949, -91.1329) radius 1
  circle C27 centre (42.0949, -72.0827) radius 1
  circle C28 centre (42.0949, -110.1829) radius 1
  circle C29 centre (41.5291, -103.3688) radius 0.1525
  circle C30 centre (41.5291, -101.2816) radius 0.1525
  circle C31 centre (50.1452, -91.1329) radius 1
  circle C32 centre (50.1452, -72.0827) radius 1
  circle C33 centre (50.1452, -110.1829) radius 1
  circle C34 centre (55.6451, -91.1329) radius 1.75
  circle C35 centre (55.6451, -72.0827) radius 1.75
  circle C36 centre (55.6451, -110.1829) radius 1.75
  circle C37 centre (55.645, -85.233) radius 0.65
  circle C38 centre (55.645, -66.1828) radius 0.65
  circle C39 centre (55.645, -104.283) radius 0.65
  circle C40 centre (60.1023, -84.2876) radius 0.1525
  circle C41 centre (60.1023, -82.2556) radius 0.1525
  circle C42 centre (60.6452, -87.3328) radius 0.65
  circle C43 centre (60.6452, -68.2826) radius 0.65
  circle C44 centre (60.6452, -106.3828) radius 0.65
  circle C45 centre (61.1452, -91.1329) radius 1
  circle C46 centre (61.1452, -72.0827) radius 1
  circle C47 centre (61.1452, -110.1829) radius 1
  circle C48 centre (60.5791, -101.3092) radius 0.1525
  circle C49 centre (60.5791, -103.3964) radius 0.1525
  circle C50 centre (69.1953, -91.1329) radius 1
  circle C51 centre (69.1953, -72.0827) radius 1
  circle C52 centre (69.1953, -110.1829) radius 1
  circle C53 centre (74.6952, -91.1329) radius 1.75
  circle C54 centre (74.6952, -72.0827) radius 1.75
  circle C55 centre (74.6952, -110.1829) radius 1.75
  circle C56 centre (74.6951, -85.233) radius 0.65
  circle C57 centre (74.6951, -66.1828) radius 0.65
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  point P163 (113.6352, -63.7757)
  point P167 (113.6352, -63.7757)
  point P42 (-0.5, -63.7757)
  point P168 (-0.5, -63.7757)
  point P169 (56.5676, -63.7757)
  point P171 (-0.5, -63.7757)
  point P43 (-0.5, -120.2758)
  point P173 (-0.5, -120.2758)
  point P175 (-0.5, -120.2758)
  point P178 (-5.3673, -67.7757)
  point P180 (3.5, -59.5204)
  point P181 (3.5, -124.4841)
  point P183 (-5.3673, -116.2758)
  point P186 (118.5025, -67.7757)
  point P179 (3.5, -67.7757)
  point P184 (109.6352, -67.7757)
  point P185 (109.6352, -59.5204)
  point P164 (113.6352, -120.2758)
  point P187 (113.6352, -120.2758)
  point P190 (118.3975, -116.2758)
  point P191 (109.6352, -124.3571)
  point P22 (108.7874, -117.8201)
  point P192 (108.7874, -117.8201)
  point P172 (3.5, -63.7757)
  point P176 (-0.5, -116.2758)
  point P177 (-0.5, -67.7757)
  point P188 (113.6352, -116.2758)
  point P189 (109.6352, -116.2758)
  coincident P163 P167
  coincident P42 P168
  midpoint L41 P169
  perpendicular L11 L42
  coincident P42 P171
  perpendicular L13 L43
  coincident P43 P173
  parallel L41 L44
  coincident P43 P175
  vertical L45
  perpendicular L43 L46
  coincident L9 P178
  perpendicular L46 L47
  coincident L7 P180
  perpendicular L7 L48
  coincident L11 P181
  perpendicular L44 L49
  coincident L9 P183
  perpendicular L9 L50
  symmetric L42 P178 P186
  symmetric L42 P179 P184
  symmetric L42 P180 P185
  coincident P164 P187
  perpendicular L19 L53
  perpendicular L53 L54
  coincident L5 P190
  perpendicular L35 L55
  coincident L3 P191
  perpendicular L3 L56
  coincident P22 P192
  dimension "d30" distance P171 P172 = 4
  dimension "d31" distance P175 P176 = 4
  dimension "d32" distance P168 P177 = 4
  dimension "d33" distance P187 P188 = 4
  dimension "d34" distance P188 P189 = 4
extrude "Extrusion12" add sketch "Esquisse11" against normal blind 7
sketch "Esquisse12" plane through (0, -6.1177, 34.695) normal (0, 0.1736, -0.9848) x axis (-1, 0, 0)
  line L1 (2.3734, -123.0658) -> (2.3734, -124.4841)
  line L2 (3.0673, -122.4887) -> (2.3734, -123.0658)
  line L3 (4.5673, -122.4887) -> (3.0673, -122.4887)
  line L4 (4.5673, -116.2758) -> (4.5673, -122.4887)
  line L5 (-3.5, -116.2758) -> (4.5673, -116.2758)
  line L6 (-3.5, -124.4841) -> (-3.5, -116.2758)
  line L7 (2.3734, -124.4841) -> (-3.5, -124.4841)
  circle C1 centre (0.5, -120.2758) radius 1
  circle C2 centre (0.5, -63.7757) radius 1
  circle C3 centre (0.5, -120.2758) radius 1
  circle C4 centre (-113.6352, -120.2758) radius 1
  circle C5 centre (-113.6352, -63.7757) radius 1
extrude "Extrusion13" add sketch "Esquisse12" profile of C1 C2 C3 C4 C5 against normal blind 4 (magnitude of "-7 mm + 3 mm")
sketch "Esquisse13" plane through (0, -7.3332, 41.5887) normal (0, -0.1736, 0.9848) x axis (1, 0, 0)
  line L1 (-3.1266, -59.5204) -> (116.1707, -59.5204)
  line L2 (-5.3673, -61.8729) -> (-3.1266, -59.5204)
  line L3 (-5.3673, -122.6858) -> (-5.3673, -61.8729)
  line L4 (-3.2047, -124.4841) -> (-5.3673, -122.6858)
  line L5 (87.375, -124.4841) -> (-3.2047, -124.4841)
  line L6 (90.0663, -120.1201) -> (87.375, -124.4841)
  line L7 (107.7241, -120.1201) -> (90.0663, -120.1201)
  line L8 (109.7424, -124.3571) -> (107.7241, -120.1201)
  line L9 (115.8162, -124.3571) -> (109.7424, -124.3571)
  line L10 (118.3975, -121.7758) -> (115.8162, -124.3571)
  line L11 (118.3975, -61.8675) -> (118.3975, -121.7758)
  line L12 (116.1707, -59.5204) -> (118.3975, -61.8675)
  line L13 (109.6352, -67.7757) -> (109.6352, -61.8204)
  line L14 (116.0975, -67.7757) -> (109.6352, -67.7757)
  line L15 (116.0975, -116.2758) -> (116.0975, -67.7757)
  line L16 (108.7874, -117.8201) -> (109.6352, -116.2758)
  line L17 (88.7826, -117.8201) -> (108.7874, -117.8201)
  line L18 (86.0912, -122.1841) -> (88.7826, -117.8201)
  line L19 (3.5, -122.1841) -> (86.0912, -122.1841)
  line L20 (3.5, -116.2758) -> (3.5, -122.1841)
  line L21 (-3.0673, -116.2758) -> (3.5, -116.2758)
  line L22 (-3.0673, -67.7757) -> (-3.0673, -116.2758)
  line L23 (3.5, -67.7757) -> (-3.0673, -67.7757)
  line L24 (3.5, -61.8204) -> (3.5, -67.7757)
  line L25 (109.6352, -61.8204) -> (3.5, -61.8204)
  line L26 (109.6352, -116.2758) -> (116.0975, -116.2758)
  circle C1 centre (113.6352, -63.7757) radius 1
  circle C2 centre (-0.5, -120.2758) radius 1
  circle C3 centre (-0.5, -63.7757) radius 1
  circle C4 centre (-0.5, -63.7757) radius 1.5
  circle C5 centre (-0.5, -120.2758) radius 1.5
  circle C6 centre (113.6352, -120.2758) radius 1.5
  circle C7 centre (113.6352, -63.7757) radius 1.5
  circle C8 centre (113.6352, -120.2758) radius 1
  concentric C3 C4
  concentric C2 C5
  concentric C1 C7
  dimension "d39" diameter C4 = 3
  dimension "d40" diameter C5 = 3
  dimension "d41" diameter C6 = 3
  dimension "d42" diameter C7 = 3
extrude "Extrusion14" cut sketch "Esquisse13" profile of C1 C2 C3 C4 C5 C6 C7 against normal blind 5
chamfer "Chanfrein1" distance 2.5
chamfer "Chanfrein2" distance 1.5
fillet "Congé2" radius 1.4
extrude "Extrusion15" add of existing geometry blind 1
sketch "Esquisse2" plane through (0, 0, 10.829) normal (0, 0, -1) x axis (1, 0, 0)
  line L1 (59.8635, 32.1887) -> (59.8635, 33.6887)
  line L2 (61.0975, 30.9735) -> (59.8635, 32.1887)
  line L3 (62.5975, 30.9735) -> (61.0975, 30.9735)
  line L4 (62.5975, -26.183) -> (62.5975, 30.9735)
  line L5 (61.0975, -26.183) -> (62.5975, -26.183)
  line L6 (60.1824, -27.1329) -> (61.0975, -26.183)
  line L7 (60.1824, -28.6329) -> (60.1824, -27.1329)
  line L8 (-57.141, -28.6329) -> (60.1824, -28.6329)
  line L9 (-57.141, -27.1329) -> (-57.141, -28.6329)
  line L10 (-58.0673, -26.1751) -> (-57.141, -27.1329)
  line L11 (-59.5673, -26.1751) -> (-58.0673, -26.1751)
  line L12 (-59.5673, 31.7455) -> (-59.5673, -26.1751)
  line L13 (-58.0673, 31.7455) -> (-59.5673, 31.7455)
  line L14 (-57.3734, 32.3138) -> (-58.0673, 31.7455)
  line L15 (-57.3734, 33.8138) -> (-57.3734, 32.3138)
  line L16 (31.9217, 33.8138) -> (-57.3734, 33.8138)
  line L17 (34.6131, 29.5161) -> (31.9217, 33.8138)
  line L18 (52.9048, 29.5161) -> (34.6131, 29.5161)
  line L19 (55.2232, 33.6887) -> (52.9048, 29.5161)
  line L20 (59.8635, 33.6887) -> (55.2232, 33.6887)
  line L21 (61.6004, -30.3827) -> (-58.5552, -30.3827)
  line L22 (64.3975, -27.4794) -> (61.6004, -30.3827)
  line L23 (64.3975, 32.3196) -> (64.3975, -27.4794)
  line L24 (61.2304, 35.4386) -> (64.3975, 32.3196)
  line L25 (54.1497, 35.4386) -> (61.2304, 35.4386)
  line L26 (51.9955, 31.5614) -> (54.1497, 35.4386)
  line L27 (35.4395, 31.5614) -> (51.9955, 31.5614)
  line L28 (32.9332, 35.5637) -> (35.4395, 31.5614)
  line L29 (-58.5662, 35.5637) -> (32.9332, 35.5637)
  line L30 (-61.3673, 33.2697) -> (-58.5662, 35.5637)
  line L31 (-61.3673, -27.4752) -> (-61.3673, 33.2697)
  line L32 (-58.5552, -30.3827) -> (-61.3673, -27.4752)
  line L33 (54.6352, -24.5983) -> (57.1352, -22.1363)
  line L34 (54.6352, -28.6329) -> (54.6352, -24.5983)
  line L35 (60.1824, -28.6329) -> (54.6352, -28.6329)
  line L36 (60.1824, -27.1329) -> (60.1824, -28.6329)
  line L37 (61.0975, -26.183) -> (60.1824, -27.1329)
  line L38 (62.5975, -26.183) -> (61.0975, -26.183)
  line L39 (62.5975, -22.1363) -> (62.5975, -26.183)
  line L40 (57.1352, -22.1363) -> (62.5975, -22.1363)
  line L41 (-54, -22.1363) -> (-51.5, -24.5983)
  line L42 (-59.5673, -22.1363) -> (-54, -22.1363)
  line L43 (-59.5673, -26.1751) -> (-59.5673, -22.1363)
  line L44 (-58.0673, -26.1751) -> (-59.5673, -26.1751)
  line L45 (-57.141, -27.1329) -> (-58.0673, -26.1751)
  line L46 (-57.141, -28.6329) -> (-57.141, -27.1329)
  line L47 (-51.5, -28.6329) -> (-57.141, -28.6329)
  line L48 (-51.5, -24.5983) -> (-51.5, -28.6329)
  line L49 (-51.5, 28.089) -> (-54, 25.627)
  line L50 (-58.0673, 31.7455) -> (-57.3734, 32.3138)
  line L51 (-59.5673, 31.7455) -> (-58.0673, 31.7455)
  line L52 (-59.5673, 25.627) -> (-59.5673, 31.7455)
  line L53 (-54, 25.627) -> (-59.5673, 25.627)
  line L54 (54.6352, 28.6738) -> (54.6352, 32.6305)
  line L55 (53.7874, 27.1479) -> (54.6352, 28.6738)
  line L56 (54.6352, 25.627) -> (53.7874, 27.1479)
  line L57 (62.5975, 25.627) -> (54.6352, 25.627)
  line L58 (62.5975, 30.9735) -> (62.5975, 25.627)
  line L59 (61.0975, 30.9735) -> (62.5975, 30.9735)
  line L60 (59.8635, 32.1887) -> (61.0975, 30.9735)
  line L61 (-51.5, 33.8138) -> (-51.5, 28.089)
  point P51 (-51.5, 28.089)
  point P64 (-51.5, 28.089)
  point P65 (-51.5, 33.8138)
  coincident P51 P64
  coincident L16 P65
  perpendicular L16 L61
loft "Lissage15" sketch "Esquisse2"
loft "Lissage16" sketch "Esquisse2"
loft "Lissage17" sketch "Esquisse2"
loft "Lissage18" sketch "Esquisse2"
extrude "Extrusion16" add of existing geometry blind 0.3
sketch "Esquisse3" plane through (0, -33.8138, 0) normal (0, 1, 0) x axis (-1, 0, 0)
  line L1 (-31.9217, 17.329) -> (51.5, 17.329)
  line L2 (-31.9217, 10.829) -> (-31.9217, 17.329)
  line L3 (51.5, 10.829) -> (-31.9217, 10.829)
  line L4 (57.3734, 10.829) -> (51.5, 10.829)
  line L5 (57.3734, 13.6637) -> (57.3734, 10.829)
  line L6 (51.5, 13.6637) -> (57.3734, 13.6637)
  line L7 (51.5, 17.329) -> (51.5, 13.6637)
  line L8 (51.5, 10.829) -> (57.3734, 10.829)
  line L9 (51.5, 13.0786) -> (51.5, 10.829)
  line L10 (57.3734, 13.0786) -> (51.5, 13.0786)
  line L11 (57.3734, 10.829) -> (57.3734, 13.0786)
extrude "Extrusion17" add sketch "Esquisse3" profile of L4 L5 L8 L9 L10 L11 along normal blind 0.4
sketch "Esquisse4" plane through (0, -4.4686, 25.3427) normal (0, -0.1736, 0.9848) x axis (1, 0, 0)
  line L1 (-54, -22.7191) -> (-51.5, -25.2191)
  line L2 (-58.0673, -22.7191) -> (-54, -22.7191)
  line L3 (-58.0673, 25.781) -> (-58.0673, -22.7191)
  line L4 (-54, 25.781) -> (-58.0673, 25.781)
  line L5 (-51.5, 28.281) -> (-54, 25.781)
  line L6 (-51.5, 31.7363) -> (-51.5, 28.281)
  line L7 (54.6352, 31.7363) -> (-51.5, 31.7363)
  line L8 (54.6352, 28.281) -> (54.6352, 31.7363)
  line L9 (57.1352, 25.781) -> (54.6352, 28.281)
  line L10 (61.0975, 25.781) -> (57.1352, 25.781)
  line L11 (61.0975, -22.7191) -> (61.0975, 25.781)
  line L12 (54.6352, -22.7191) -> (61.0975, -22.7191)
  line L13 (53.7874, -24.2634) -> (54.6352, -22.7191)
  line L14 (33.7826, -24.2634) -> (53.7874, -24.2634)
  line L15 (31.0912, -28.6274) -> (33.7826, -24.2634)
  line L16 (-51.5, -28.6274) -> (31.0912, -28.6274)
  line L17 (-51.5, -25.2191) -> (-51.5, -28.6274)
  line L18 (63.3975, 31.6893) -> (63.3975, -28.2191)
  line L19 (61.1707, 34.0363) -> (63.3975, 31.6893)
  line L20 (-58.1266, 34.0363) -> (61.1707, 34.0363)
  line L21 (-60.3673, 31.6839) -> (-58.1266, 34.0363)
  line L22 (-60.3673, -29.1291) -> (-60.3673, 31.6839)
  line L23 (-58.2047, -30.9274) -> (-60.3673, -29.1291)
  line L24 (32.375, -30.9274) -> (-58.2047, -30.9274)
  line L25 (35.0663, -26.5634) -> (32.375, -30.9274)
  line L26 (52.7241, -26.5634) -> (35.0663, -26.5634)
  line L27 (54.7424, -30.8004) -> (52.7241, -26.5634)
  line L28 (60.8162, -30.8004) -> (54.7424, -30.8004)
  line L29 (63.3975, -28.2191) -> (60.8162, -30.8004)
  line L30 (-30.4073, 28.1263) -> (-37.5073, 28.1263)
  line L31 (-30.4073, 20.6263) -> (-30.4073, 28.1263)
  line L32 (-37.5073, 20.6263) -> (-30.4073, 20.6263)
  line L33 (-37.5073, 28.1263) -> (-37.5073, 20.6263)
  line L34 (-37.5073, 15.0063) -> (-30.4073, 20.6263)
  line L35 (-37.5073, 20.6263) -> (-37.5073, 15.0063)
  line L36 (-37.5073, 22.5063) -> (-30.4073, 28.1263)
  line L37 (-37.5073, 15.0063) -> (-37.5073, 22.5063)
  line L38 (-37.5073, 15.0063) -> (-30.4073, 20.6263)
  line L39 (-30.4073, 28.1263) -> (-30.4073, 20.6263)
  line L40 (-30.4073, 28.1263) -> (-37.5073, 22.5063)
  line L41 (-30.4073, 8.5263) -> (-30.4073, 1.0263)
  line L42 (-37.5073, -4.5937) -> (-30.4073, 1.0263)
  line L43 (-37.5073, -4.5937) -> (-37.5073, 2.9063)
  line L44 (-30.4073, 8.5263) -> (-37.5073, 2.9063)
  line L45 (-30.4073, -10.4737) -> (-30.4073, -17.9737)
  line L46 (-37.5073, -23.5937) -> (-30.4073, -17.9737)
  line L47 (-37.5073, -23.5937) -> (-37.5073, -16.0937)
  line L48 (-30.4073, -10.4737) -> (-37.5073, -16.0937)
  line L49 (-40, 41) -> (-40, 10)
  line L50 (-28, 34.0363) -> (-40, 34.0363)
  line L51 (-28, -30.9274) -> (-28, 34.0363)
  line L52 (-40, -30.9274) -> (-28, -30.9274)
  line L53 (-40, 34.0363) -> (-40, -30.9274)
  circle C1 centre (58.6352, -26.7191) radius 1.5
  circle C2 centre (-55.5, -26.7191) radius 1.5
  circle C3 centre (58.6352, 29.781) radius 1.5
  circle C4 centre (-55.5, 29.781) radius 1.5
  point P56 (-28, -30.9274)
  point P54 (-40, 34.0363)
  point P35 (-37.5073, 28.1263)
  point P36 (-30.4073, 28.1263)
  point P38 (-37.5073, 20.6263)
  point P39 (-37.5073, 15.0063)
  point P55 (-28, 34.0363)
  horizontal L30
  vertical L31
  horizontal L32
  vertical L33
  perpendicular L32 L35
  perpendicular L32 L37
  perpendicular L30 L39
  parallel L36 L40
  vertical L49
  horizontal L50
  vertical L51
  horizontal L52
  vertical L53
  coincident L24 P56
  coincident L49 P54
  coincident L20 P54
  dimension "d102" distance P35 P36 = 7.1
  dimension "d103" distance P35 P38 = 7.5
  dimension "d104" distance P38 P39 = 5.62
  dimension "d105" distance L20 L30 = 5.91
  dimension "d106" distance L22 L33 = 22.86
  dimension "d107" distance P54 P55 = 12
extrude "Extrusion18" add sketch "Esquisse4" profile of L7 L16 L20 L24 L37 L38 L39 L40 L41 L42 L43 L44 L45 L46 L47 L48 L50 L51 L52 L53 against normal blind 4
sketch "Esquisse5" plane through (0, -3.774, 21.4035) normal (0, 0.1736, -0.9848) x axis (-1, 0, 0)
  line L1 (28, 32.9068) -> (40, 32.9068)
  line L2 (28, -30.5032) -> (28, 32.9068)
  line L3 (40, -30.5032) -> (28, -30.5032)
  line L4 (40, 32.9068) -> (40, -30.5032)
  line L5 (30.4073, 28.1263) -> (30.4073, 20.6263)
  line L6 (37.5073, 22.5063) -> (30.4073, 28.1263)
  line L7 (37.5073, 15.0063) -> (37.5073, 22.5063)
  line L8 (30.4073, 20.6263) -> (37.5073, 15.0063)
  line L9 (30.4073, -10.4737) -> (30.4073, -17.9737)
  line L10 (37.5073, -16.0937) -> (30.4073, -10.4737)
  line L11 (37.5073, -23.5937) -> (37.5073, -16.0937)
  line L12 (30.4073, -17.9737) -> (37.5073, -23.5937)
  line L13 (30.4073, 8.5263) -> (30.4073, 1.0263)
  line L14 (37.5073, 2.9063) -> (30.4073, 8.5263)
  line L15 (37.5073, -4.5937) -> (37.5073, 2.9063)
  line L16 (30.4073, 1.0263) -> (37.5073, -4.5937)
  line L17 (38.5, 31.4068) -> (38.5, -29.0032)
  line L18 (29.5, 31.4068) -> (38.5, 31.4068)
  line L19 (29.5, -29.0032) -> (29.5, 31.4068)
  line L20 (38.5, -29.0032) -> (29.5, -29.0032)
  dimension "d110" = -1.5
sketch "Esquisse6" plane through (0, -33.8138, 0) normal (0, 1, 0) x axis (-1, 0, 0)
  line L1 (28, 17.329) -> (28, 16.1066)
  line L2 (-31.9217, 17.329) -> (28, 17.329)
  line L3 (-31.9217, 10.829) -> (-31.9217, 17.329)
  line L4 (51.5, 10.829) -> (-31.9217, 10.829)
  line L5 (51.5, 13.0786) -> (51.5, 10.829)
  line L6 (57.3734, 13.0786) -> (51.5, 13.0786)
  line L7 (57.3734, 13.6637) -> (57.3734, 13.0786)
  line L8 (51.5, 13.6637) -> (57.3734, 13.6637)
  line L9 (51.5, 17.329) -> (51.5, 13.6637)
  line L10 (40, 17.329) -> (51.5, 17.329)
  line L11 (40, 16.1066) -> (40, 17.329)
  line L12 (28, 16.1066) -> (40, 16.1066)
  line L13 (51.5, 13.6637) -> (51.5, 13.0786)
  point P7 (51.5, 13.0786)
  point P14 (51.5, 13.0786)
  coincident P7 P14
  perpendicular L8 L13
